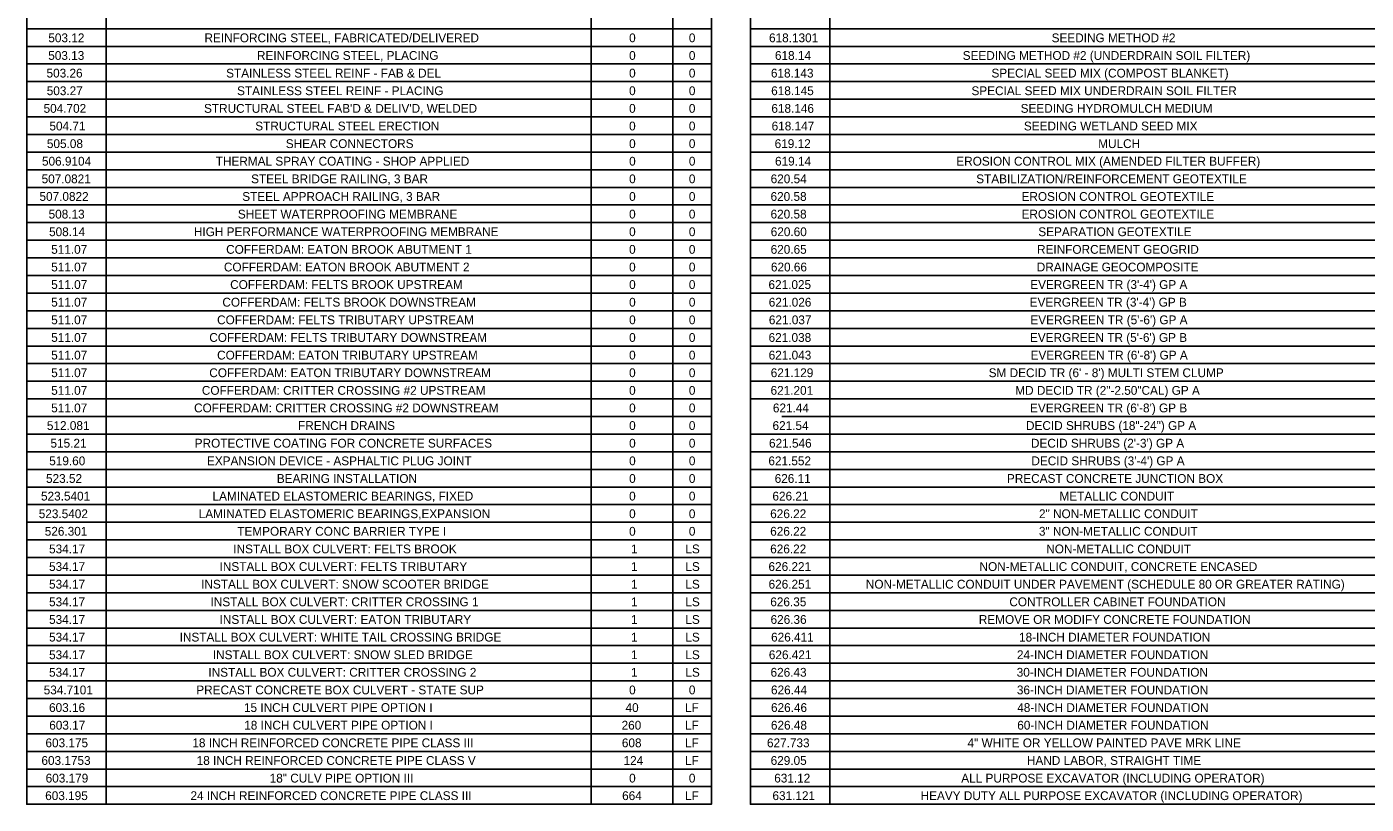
# Model space of a CAD drawing. Extents: x -18.7 to 5.6, y -2.7 to 5.1.
# Drawn here: x 3.137 to 4.632, y 0.019 to 0.887 of the extents above; entities that cross this region are included whole.
import ezdxf

# ---------------------------------------------------------------- set-up
doc = ezdxf.new("R2010")
doc.units = 0
doc.layers.add('ANNOTATION', color=7, linetype='Continuous')
doc.layers.add('BORDER', color=7, linetype='Continuous')

msp = doc.modelspace()

# ---------------------------------------------------------------- linework, layer by layer
at = {"layer": 'BORDER'}
for p, q in [((3.2255, 1.7315), (3.2255, 0.0189)), ((3.7669, 1.7315), (3.7669, 0.0189)), ((3.8583, 1.7315), (3.8583, 0.0189)), ((4.0334, 1.7315), (4.0334, 0.0189)), ((3.1369, 0.885), (3.9012, 0.885)), ((3.9448, 0.885), (4.8091, 0.885)), ((3.1369, 0.8654), (3.9012, 0.8654)), ((3.9448, 0.8654), (4.8091, 0.8654)), ((3.1369, 0.8457), (3.9012, 0.8457)), ((3.9448, 0.8457), (4.8091, 0.8457)), ((3.1369, 0.826), (3.9012, 0.826)), ((3.9448, 0.826), (4.8091, 0.826)), ((3.1369, 0.8063), (3.9012, 0.8063)), ((3.9448, 0.8063), (4.8091, 0.8063)), ((3.1369, 0.7866), (3.9012, 0.7866)), ((3.9448, 0.7866), (4.8091, 0.7866)), ((3.1369, 0.7669), (3.9012, 0.7669)), ((3.9448, 0.7669), (4.8091, 0.7669)), ((3.1369, 0.7472), (3.9012, 0.7472)), ((3.9448, 0.7472), (4.8091, 0.7472)), ((3.1369, 0.7276), (3.9012, 0.7276)), ((3.9448, 0.7276), (4.8091, 0.7276)), ((3.1369, 0.7079), (3.9012, 0.7079)), ((3.9448, 0.7079), (4.8091, 0.7079)), ((3.1369, 0.6882), (3.9012, 0.6882)), ((3.9448, 0.6882), (4.8091, 0.6882)), ((3.1369, 0.6685), (3.9012, 0.6685)), ((3.9448, 0.6685), (4.8091, 0.6685)), ((3.1369, 0.6488), (3.9012, 0.6488)), ((3.9448, 0.6488), (4.8091, 0.6488)), ((3.1369, 0.6291), (3.9012, 0.6291)), ((3.9448, 0.6291), (4.8091, 0.6291)), ((3.1369, 0.6094), (3.9012, 0.6094)), ((3.9448, 0.6094), (4.8091, 0.6094)), ((3.1369, 0.5898), (3.9012, 0.5898)), ((3.9448, 0.5898), (4.8091, 0.5898)), ((3.1369, 0.5701), (3.9012, 0.5701)), ((3.9448, 0.5701), (4.8091, 0.5701)), ((3.1369, 0.5504), (3.9012, 0.5504)), ((3.9448, 0.5504), (4.8091, 0.5504)), ((3.1369, 0.5307), (3.9012, 0.5307)), ((3.9448, 0.5307), (4.8091, 0.5307)), ((3.1369, 0.511), (3.9012, 0.511)), ((3.9448, 0.511), (4.8091, 0.511)), ((3.1369, 0.4913), (3.9012, 0.4913)), ((3.9448, 0.4913), (4.8091, 0.4913)), ((3.1369, 0.4716), (3.9012, 0.4716)), ((3.9448, 0.4716), (4.8091, 0.4716)), ((3.1369, 0.452), (3.9012, 0.452)), ((3.9799, 0.452), (4.8091, 0.452)), ((3.1369, 0.4323), (3.9012, 0.4323)), ((3.9448, 0.4323), (4.8091, 0.4323)), ((3.1369, 0.4126), (3.9012, 0.4126)), ((3.9448, 0.4126), (4.8091, 0.4126)), ((3.1369, 0.3929), (3.9012, 0.3929)), ((3.9448, 0.3929), (4.8091, 0.3929)), ((3.1369, 0.3732), (3.9012, 0.3732)), ((3.9448, 0.3732), (4.8091, 0.3732)), ((3.1369, 0.3535), (3.9012, 0.3535)), ((3.9448, 0.3535), (4.8091, 0.3535)), ((3.1369, 0.3338), (3.9012, 0.3338)), ((3.9448, 0.3338), (4.8091, 0.3338)), ((3.1369, 0.3142), (3.9012, 0.3142)), ((3.9448, 0.3142), (4.8091, 0.3142)), ((3.1369, 0.2945), (3.9012, 0.2945)), ((3.9448, 0.2945), (4.8091, 0.2945)), ((3.1369, 0.2748), (3.9012, 0.2748)), ((3.9448, 0.2748), (4.8091, 0.2748)), ((3.1369, 0.2551), (3.9012, 0.2551)), ((3.9448, 0.2551), (4.8091, 0.2551)), ((3.1369, 0.2354), (3.9012, 0.2354)), ((3.9448, 0.2354), (4.8091, 0.2354)), ((3.1369, 0.2157), (3.9012, 0.2157)), ((3.9448, 0.2157), (4.8091, 0.2157)), ((3.1369, 0.196), (3.9012, 0.196)), ((3.9448, 0.196), (4.8091, 0.196)), ((3.1369, 0.1764), (3.9012, 0.1764)), ((3.9448, 0.1764), (4.8091, 0.1764)), ((3.1369, 0.1567), (3.9012, 0.1567)), ((3.9448, 0.1567), (4.8091, 0.1567)), ((3.1369, 0.137), (3.9012, 0.137)), ((3.9448, 0.137), (4.8091, 0.137)), ((3.1369, 0.1173), (3.9012, 0.1173)), ((3.9448, 0.1173), (4.8091, 0.1173)), ((3.1369, 0.0976), (3.9012, 0.0976)), ((3.9448, 0.0976), (4.8091, 0.0976)), ((3.1369, 0.0779), (3.9012, 0.0779)), ((3.9448, 0.0779), (4.8091, 0.0779)), ((3.1369, 0.0582), (3.9012, 0.0582)), ((3.9448, 0.0582), (4.8091, 0.0582)), ((3.1369, 0.0386), (3.9012, 0.0386)), ((3.9448, 0.0386), (4.8091, 0.0386)), ((3.1369, 0.0189), (3.9012, 0.0189))]:
    msp.add_line(p, q, dxfattribs=at)
for points in [[(3.1369, 1.7512), (3.9012, 1.7512), (3.9012, 0.0189), (3.1369, 0.0189)], [(3.9448, 1.7512), (4.8091, 1.7512), (4.8091, 0.0189), (3.9448, 0.0189)]]:
    msp.add_lwpolyline(points, close=True, dxfattribs=at)

# ---------------------------------------------------------------- texts
at = {"layer": 'ANNOTATION'}
for s, height, p in [('503.12', 0.00984, (3.161, 0.87)), ('REINFORCING STEEL, FABRICATED/DELIVERED', 0.009843, (3.3353, 0.87)), ('0', 0.00984, (3.8094, 0.87)), ('0', 0.00984, (3.8761, 0.87)), ('618.1301', 0.00984, (3.9656, 0.87)), ('SEEDING METHOD #2', 0.009843, (4.2811, 0.87)), ('503.13', 0.00984, (3.1609, 0.8503)), ('REINFORCING STEEL, PLACING', 0.009843, (3.3939, 0.8503)), ('0', 0.00984, (3.8094, 0.8503)), ('0', 0.00984, (3.8761, 0.8503)), ('618.14', 0.00984, (3.9722, 0.8503)), ('SEEDING METHOD #2 (UNDERDRAIN SOIL FILTER)', 0.009843, (4.1818, 0.8503)), ('503.26', 0.00984, (3.159, 0.8306)), ('STAINLESS STEEL REINF - FAB & DEL', 0.009843, (3.3595, 0.8306)), ('0', 0.00984, (3.8094, 0.8306)), ('0', 0.00984, (3.8761, 0.8306)), ('618.143', 0.00984, (3.9677, 0.8306)), ('SPECIAL SEED MIX (COMPOST BLANKET)', 0.009843, (4.2139, 0.8306)), ('503.27', 0.00984, (3.1592, 0.8109)), ('STAINLESS STEEL REINF - PLACING', 0.009843, (3.3717, 0.8109)), ('0', 0.00984, (3.8094, 0.8109)), ('0', 0.00984, (3.8761, 0.8109)), ('618.145', 0.00984, (3.968, 0.8109)), ('SPECIAL SEED MIX UNDERDRAIN SOIL FILTER', 0.009843, (4.1916, 0.8109)), ('504.702', 0.00984, (3.1557, 0.7912)), ("STRUCTURAL STEEL FAB'D & DELIV'D, WELDED", 0.009843, (3.3348, 0.7912)), ('0', 0.00984, (3.8094, 0.7912)), ('0', 0.00984, (3.8761, 0.7912)), ('618.146', 0.00984, (3.9682, 0.7912)), ('SEEDING HYDROMULCH MEDIUM', 0.009843, (4.2465, 0.7912)), ('504.71', 0.00984, (3.1622, 0.7715)), ('STRUCTURAL STEEL ERECTION', 0.009843, (3.392, 0.7715)), ('0', 0.00984, (3.8094, 0.7715)), ('0', 0.00984, (3.8761, 0.7715)), ('618.147', 0.00984, (3.9685, 0.7715)), ('SEEDING WETLAND SEED MIX', 0.009843, (4.2501, 0.7715)), ('505.08', 0.00984, (3.1594, 0.7518)), ('SHEAR CONNECTORS', 0.009843, (3.4261, 0.7518)), ('0', 0.00984, (3.8094, 0.7518)), ('0', 0.00984, (3.8761, 0.7518)), ('619.12', 0.00984, (3.9719, 0.7518)), ('MULCH', 0.00984, (4.3331, 0.7518)), ('506.9104', 0.00984, (3.1539, 0.7322)), ('THERMAL SPRAY COATING - SHOP APPLIED', 0.009843, (3.3479, 0.7322)), ('0', 0.00984, (3.8094, 0.7322)), ('0', 0.00984, (3.8761, 0.7322)), ('619.14', 0.00984, (3.9723, 0.7322)), ('EROSION CONTROL MIX (AMENDED FILTER BUFFER)', 0.009843, (4.1747, 0.7322)), ('507.0821', 0.00984, (3.1535, 0.7125)), ('STEEL BRIDGE RAILING, 3 BAR', 0.009843, (3.3874, 0.7125)), ('0', 0.00984, (3.8094, 0.7125)), ('0', 0.00984, (3.8761, 0.7125)), ('620.54', 0.00984, (3.9674, 0.7125)), ('STABILIZATION/REINFORCEMENT GEOTEXTILE', 0.009843, (4.1969, 0.7125)), ('507.0822', 0.00984, (3.1511, 0.6928)), ('STEEL APPROACH RAILING, 3 BAR', 0.009843, (3.3775, 0.6928)), ('0', 0.00984, (3.8094, 0.6928)), ('0', 0.00984, (3.8761, 0.6928)), ('620.58', 0.00984, (3.9673, 0.6928)), ('EROSION CONTROL GEOTEXTILE', 0.009843, (4.2475, 0.6928)), ('508.13', 0.00984, (3.1613, 0.6731)), ('SHEET WATERPROOFING MEMBRANE', 0.009843, (3.3726, 0.6731)), ('0', 0.00984, (3.8094, 0.6731)), ('0', 0.00984, (3.8761, 0.6731)), ('620.58', 0.00984, (3.9673, 0.6731)), ('EROSION CONTROL GEOTEXTILE', 0.009843, (4.2475, 0.6731)), ('508.14', 0.00984, (3.1618, 0.6534)), ('HIGH PERFORMANCE WATERPROOFING MEMBRANE', 0.009843, (3.3235, 0.6534)), ('0', 0.00984, (3.8094, 0.6534)), ('0', 0.00984, (3.8761, 0.6534)), ('620.60', 0.00984, (3.9675, 0.6534)), ('SEPARATION GEOTEXTILE', 0.009843, (4.2662, 0.6534)), ('511.07', 0.00984, (3.1642, 0.6337)), ('COFFERDAM: EATON BROOK ABUTMENT 1', 0.009843, (3.3595, 0.6337)), ('0', 0.00984, (3.8094, 0.6337)), ('0', 0.00984, (3.8761, 0.6337)), ('620.65', 0.00984, (3.9674, 0.6337)), ('REINFORCEMENT GEOGRID', 0.009843, (4.2648, 0.6337)), ('511.07', 0.00984, (3.1642, 0.614)), ('COFFERDAM: EATON BROOK ABUTMENT 2', 0.009843, (3.357, 0.614)), ('0', 0.00984, (3.8094, 0.614)), ('0', 0.00984, (3.8761, 0.614)), ('620.66', 0.00984, (3.9677, 0.614)), ('DRAINAGE GEOCOMPOSITE', 0.009843, (4.2645, 0.614)), ('511.07', 0.00984, (3.1642, 0.5944)), ('COFFERDAM: FELTS BROOK UPSTREAM', 0.009843, (3.364, 0.5944)), ('0', 0.00984, (3.8094, 0.5944)), ('0', 0.00984, (3.8761, 0.5944)), ('621.025', 0.00984, (3.965, 0.5944)), ("EVERGREEN TR (3'-4') GP A", 0.009843, (4.2572, 0.5944)), ('511.07', 0.00984, (3.1642, 0.5747)), ('COFFERDAM: FELTS BROOK DOWNSTREAM', 0.009843, (3.3553, 0.5747)), ('0', 0.00984, (3.8094, 0.5747)), ('0', 0.00984, (3.8761, 0.5747)), ('621.026', 0.00984, (3.9653, 0.5747)), ("EVERGREEN TR (3'-4') GP B", 0.009843, (4.2566, 0.5747)), ('511.07', 0.00984, (3.1642, 0.555)), ('COFFERDAM: FELTS TRIBUTARY UPSTREAM', 0.009843, (3.3494, 0.555)), ('0', 0.00984, (3.8094, 0.555)), ('0', 0.00984, (3.8761, 0.555)), ('621.037', 0.00984, (3.9654, 0.555)), ("EVERGREEN TR (5'-6') GP A", 0.009843, (4.2574, 0.555)), ('511.07', 0.00984, (3.1642, 0.5353)), ('COFFERDAM: FELTS TRIBUTARY DOWNSTREAM', 0.009843, (3.3407, 0.5353)), ('0', 0.00984, (3.8094, 0.5353)), ('0', 0.00984, (3.8761, 0.5353)), ('621.038', 0.00984, (3.9651, 0.5353)), ("EVERGREEN TR (5'-6') GP B", 0.009843, (4.2569, 0.5353)), ('511.07', 0.00984, (3.1642, 0.5156)), ('COFFERDAM: EATON TRIBUTARY UPSTREAM', 0.009843, (3.3494, 0.5156)), ('0', 0.00984, (3.8094, 0.5156)), ('0', 0.00984, (3.8761, 0.5156)), ('621.043', 0.00984, (3.9652, 0.5156)), ("EVERGREEN TR (6'-8') GP A", 0.009843, (4.2576, 0.5156)), ('511.07', 0.00984, (3.1642, 0.4959)), ('COFFERDAM: EATON TRIBUTARY DOWNSTREAM', 0.009843, (3.3407, 0.4959)), ('0', 0.00984, (3.8094, 0.4959)), ('0', 0.00984, (3.8761, 0.4959)), ('621.129', 0.00984, (3.9675, 0.4959)), ("SM DECID TR (6' - 8') MULTI STEM CLUMP", 0.009843, (4.2108, 0.4959)), ('511.07', 0.00984, (3.1642, 0.4762)), ('COFFERDAM: CRITTER CROSSING #2 UPSTREAM', 0.009843, (3.3324, 0.4762)), ('0', 0.00984, (3.8094, 0.4762)), ('0', 0.00984, (3.8761, 0.4762)), ('621.201', 0.00984, (3.9673, 0.4762)), ('MD DECID TR (2"-2.50"CAL) GP A', 0.009843, (4.2405, 0.4762)), ('511.07', 0.00984, (3.1642, 0.4566)), ('COFFERDAM: CRITTER CROSSING #2 DOWNSTREAM', 0.009843, (3.3237, 0.4566)), ('0', 0.00984, (3.8094, 0.4566)), ('0', 0.00984, (3.8761, 0.4566)), ('621.44', 0.00984, (3.9699, 0.4566)), ("EVERGREEN TR (6'-8') GP B", 0.009843, (4.257, 0.4566)), ('512.081', 0.00984, (3.1594, 0.4369)), ('FRENCH DRAINS', 0.009843, (3.4398, 0.4369)), ('0', 0.00984, (3.8094, 0.4369)), ('0', 0.00984, (3.8761, 0.4369)), ('621.54', 0.00984, (3.9695, 0.4369)), ('DECID SHRUBS (18"-24") GP A', 0.009843, (4.2525, 0.4369)), ('515.21', 0.00984, (3.1634, 0.4172)), ('PROTECTIVE COATING FOR CONCRETE SURFACES', 0.009843, (3.3244, 0.4172)), ('0', 0.00984, (3.8094, 0.4172)), ('0', 0.00984, (3.8761, 0.4172)), ('621.546', 0.00984, (3.9656, 0.4172)), ("DECID SHRUBS (2'-3') GP A", 0.009843, (4.258, 0.4172)), ('519.60', 0.00984, (3.162, 0.3975)), ('EXPANSION DEVICE - ASPHALTIC PLUG JOINT', 0.009843, (3.3381, 0.3975)), ('0', 0.00984, (3.8094, 0.3975)), ('0', 0.00984, (3.8761, 0.3975)), ('621.552', 0.00984, (3.9649, 0.3975)), ("DECID SHRUBS (3'-4') GP A", 0.009843, (4.2585, 0.3975)), ('523.52', 0.00984, (3.1584, 0.3778)), ('BEARING INSTALLATION', 0.009843, (3.4161, 0.3778)), ('0', 0.00984, (3.8094, 0.3778)), ('0', 0.00984, (3.8761, 0.3778)), ('626.11', 0.00984, (3.9719, 0.3778)), ('PRECAST CONCRETE JUNCTION BOX', 0.009843, (4.2312, 0.3778)), ('523.5401', 0.00984, (3.1528, 0.3581)), ('LAMINATED ELASTOMERIC BEARINGS, FIXED', 0.009843, (3.3443, 0.3581)), ('0', 0.00984, (3.8094, 0.3581)), ('0', 0.00984, (3.8761, 0.3581)), ('626.21', 0.00984, (3.9694, 0.3581)), ('METALLIC CONDUIT', 0.009843, (4.2899, 0.3581)), ('523.5402', 0.00984, (3.1503, 0.3384)), ('LAMINATED ELASTOMERIC BEARINGS,EXPANSION', 0.009843, (3.3289, 0.3384)), ('0', 0.00984, (3.8094, 0.3384)), ('0', 0.00984, (3.8761, 0.3384)), ('626.22', 0.00984, (3.9669, 0.3384)), ('2" NON-METALLIC CONDUIT', 0.009843, (4.267, 0.3384)), ('526.301', 0.00984, (3.157, 0.3188)), ('TEMPORARY CONC BARRIER TYPE I', 0.009843, (3.3719, 0.3188)), ('0', 0.00984, (3.8094, 0.3188)), ('0', 0.00984, (3.8761, 0.3188)), ('626.22', 0.00984, (3.9669, 0.3188)), ('3" NON-METALLIC CONDUIT', 0.009843, (4.2669, 0.3188)), ('534.17', 0.00984, (3.1618, 0.2991)), ('INSTALL BOX CULVERT: FELTS BROOK', 0.009843, (3.3675, 0.2991)), ('1', 0.00984, (3.8115, 0.2991)), ('LS', 0.00984, (3.8722, 0.2991)), ('626.22', 0.00984, (3.9669, 0.2991)), ('NON-METALLIC CONDUIT', 0.009843, (4.2751, 0.2991)), ('534.17', 0.00984, (3.1618, 0.2794)), ('INSTALL BOX CULVERT: FELTS TRIBUTARY', 0.009843, (3.3522, 0.2794)), ('1', 0.00984, (3.8115, 0.2794)), ('LS', 0.00984, (3.8722, 0.2794)), ('626.221', 0.00984, (3.965, 0.2794)), ('NON-METALLIC CONDUIT, CONCRETE ENCASED', 0.009843, (4.2006, 0.2794)), ('534.17', 0.00984, (3.1618, 0.2597)), ('INSTALL BOX CULVERT: SNOW SCOOTER BRIDGE', 0.009843, (3.3316, 0.2597)), ('1', 0.00984, (3.8115, 0.2597)), ('LS', 0.00984, (3.8722, 0.2597)), ('626.251', 0.00984, (3.9651, 0.2597)), ('NON-METALLIC CONDUIT UNDER PAVEMENT (SCHEDULE 80 OR GREATER RATING)', 0.009843, (4.0737, 0.2597)), ('534.17', 0.00984, (3.1618, 0.24)), ('INSTALL BOX CULVERT: CRITTER CROSSING 1', 0.009843, (3.3421, 0.24)), ('1', 0.00984, (3.8115, 0.24)), ('LS', 0.00984, (3.8722, 0.24)), ('626.35', 0.00984, (3.967, 0.24)), ('CONTROLLER CABINET FOUNDATION', 0.009843, (4.2339, 0.24)), ('534.17', 0.00984, (3.1618, 0.2203)), ('INSTALL BOX CULVERT: EATON TRIBUTARY', 0.009843, (3.3522, 0.2203)), ('1', 0.00984, (3.8115, 0.2203)), ('LS', 0.00984, (3.8722, 0.2203)), ('626.36', 0.00984, (3.9673, 0.2203)), ('REMOVE OR MODIFY CONCRETE FOUNDATION', 0.009843, (4.1998, 0.2203)), ('534.17', 0.00984, (3.1618, 0.2006)), ('INSTALL BOX CULVERT: WHITE TAIL CROSSING BRIDGE', 0.009843, (3.3076, 0.2006)), ('1', 0.00984, (3.8115, 0.2006)), ('LS', 0.00984, (3.8722, 0.2006)), ('626.411', 0.00984, (3.9679, 0.2006)), ('18-INCH DIAMETER FOUNDATION', 0.009843, (4.2447, 0.2006)), ('534.17', 0.00984, (3.1618, 0.1809)), ('INSTALL BOX CULVERT: SNOW SLED BRIDGE', 0.009843, (3.3446, 0.1809)), ('1', 0.00984, (3.8115, 0.1809)), ('LS', 0.00984, (3.8722, 0.1809)), ('626.421', 0.00984, (3.9654, 0.1809)), ('24-INCH DIAMETER FOUNDATION', 0.009843, (4.2424, 0.1809)), ('534.17', 0.00984, (3.1618, 0.1613)), ('INSTALL BOX CULVERT: CRITTER CROSSING 2', 0.009843, (3.3397, 0.1613)), ('1', 0.00984, (3.8115, 0.1613)), ('LS', 0.00984, (3.8722, 0.1613)), ('626.43', 0.00984, (3.9673, 0.1613)), ('30-INCH DIAMETER FOUNDATION', 0.009843, (4.2421, 0.1613)), ('534.7101', 0.00984, (3.1558, 0.1416)), ('PRECAST CONCRETE BOX CULVERT - STATE SUP', 0.009843, (3.3262, 0.1416)), ('0', 0.00984, (3.8094, 0.1416)), ('0', 0.00984, (3.8761, 0.1416)), ('626.44', 0.00984, (3.9678, 0.1416)), ('36-INCH DIAMETER FOUNDATION', 0.009843, (4.2423, 0.1416)), ('603.16', 0.00984, (3.1618, 0.1219)), ('15 INCH CULVERT PIPE OPTION I', 0.009843, (3.3794, 0.1219)), ('40', 0.00984, (3.8054, 0.1219)), ('LF', 0.00984, (3.8718, 0.1219)), ('626.46', 0.00984, (3.9678, 0.1219)), ('48-INCH DIAMETER FOUNDATION', 0.009843, (4.2427, 0.1219)), ('603.17', 0.00984, (3.162, 0.1022)), ('18 INCH CULVERT PIPE OPTION I', 0.009843, (3.3797, 0.1022)), ('260', 0.00984, (3.801, 0.1022)), ('LF', 0.00984, (3.8718, 0.1022)), ('626.48', 0.00984, (3.9677, 0.1022)), ('60-INCH DIAMETER FOUNDATION', 0.009843, (4.2427, 0.1022)), ('603.175', 0.00984, (3.1578, 0.0825)), ('18 INCH REINFORCED CONCRETE PIPE CLASS III', 0.009843, (3.3218, 0.0825)), ('608', 0.00984, (3.8013, 0.0825)), ('LF', 0.00984, (3.8718, 0.0825)), ('627.733', 0.00984, (3.9633, 0.0825)), ('4" WHITE OR YELLOW PAINTED PAVE MRK LINE', 0.009843, (4.1872, 0.0825)), ('603.1753', 0.00984, (3.1533, 0.0628)), ('18 INCH REINFORCED CONCRETE PIPE CLASS V', 0.009843, (3.3266, 0.0628)), ('124', 0.00984, (3.8032, 0.0628)), ('LF', 0.00984, (3.8718, 0.0628)), ('629.05', 0.00984, (3.9674, 0.0628)), ('HAND LABOR, STRAIGHT TIME', 0.009843, (4.2535, 0.0628)), ('603.179', 0.00984, (3.158, 0.0431)), ('18" CULV PIPE OPTION III', 0.009843, (3.4081, 0.0431)), ('0', 0.00984, (3.8094, 0.0431)), ('0', 0.00984, (3.8761, 0.0431)), ('631.12', 0.00984, (3.9714, 0.0431)), ('ALL PURPOSE EXCAVATOR (INCLUDING OPERATOR)', 0.009843, (4.1802, 0.0431)), ('603.195', 0.00984, (3.1575, 0.0235)), ('24 INCH REINFORCED CONCRETE PIPE CLASS III', 0.009843, (3.3197, 0.0235)), ('664', 0.00984, (3.8016, 0.0235)), ('LF', 0.00984, (3.8718, 0.0235)), ('631.121', 0.00984, (3.9694, 0.0235)), ('HEAVY DUTY ALL PURPOSE EXCAVATOR (INCLUDING OPERATOR)', 0.009843, (4.1348, 0.0235))]:
    msp.add_text(s, height=height, dxfattribs=at).set_placement(p)

doc.saveas('drawing.dxf')
